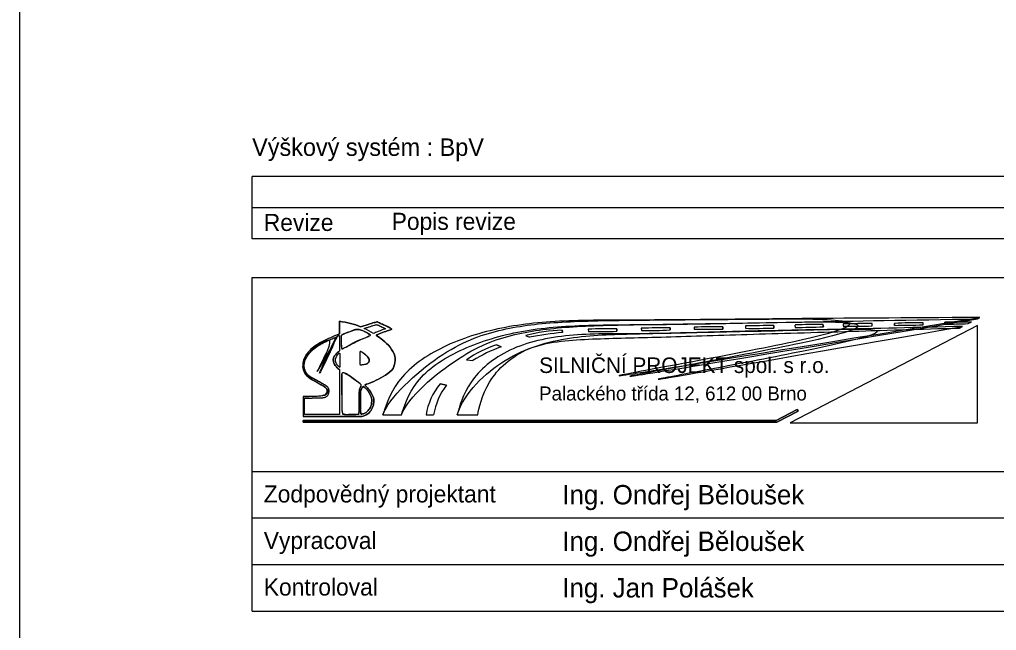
# Model space of a CAD drawing. Extents: x -598463 to -597973, y -1203201 to -1202904.
# Drawn here: x -598183.2 to -598057.2, y -1203061.8 to -1202983 of the extents above; entities that cross this region are included whole.
import ezdxf

# ---------------------------------------------------------------- set-up
doc = ezdxf.new("R2010")
doc.units = 0
for name, color, linetype in [('AQP_ROZPISKA', 7, 'Continuous'), ('geom_Pomoc', 7, 'Continuous'), ('sil_popis_legenda', 7, 'Continuous')]:
    doc.layers.add(name, color=color, linetype=linetype)

msp = doc.modelspace()

# ---------------------------------------------------------------- linework, layer by layer
at = {"layer": 'AQP_ROZPISKA'}
for p, q in [((-597983.21, -1203003.29), (-598153.21, -1203003.29)), ((-598153.21, -1203011.29), (-598153.21, -1203003.29)), ((-597983.21, -1203007.29), (-598153.21, -1203007.29)), ((-597983.21, -1203011.29), (-598153.21, -1203011.29)), ((-598141.96, -1203023.56), (-598141.96, -1203021.94)), ((-598141.96, -1203021.94), (-598141.96, -1203023.56)), ((-598089.57, -1203022.54), (-598089.59, -1203022.84)), ((-598089.57, -1203022.54), (-598089.59, -1203022.84)), ((-598085.93, -1203022.48), (-598085.91, -1203022.8)), ((-598085.91, -1203022.8), (-598085.93, -1203022.48)), ((-598059.65, -1203022.46), (-598083.83, -1203035.04)), ((-598059.65, -1203022.46), (-598083.83, -1203035.04)), ((-598083.19, -1203022.42), (-598083.18, -1203022.73)), ((-598083.19, -1203022.42), (-598083.18, -1203022.73)), ((-598079.58, -1203022.35), (-598079.52, -1203022.66)), ((-598079.52, -1203022.66), (-598079.58, -1203022.35)), ((-598076.97, -1203022.28), (-598076.96, -1203022.58)), ((-598076.97, -1203022.28), (-598076.96, -1203022.58)), ((-598073.23, -1203022.53), (-598073.24, -1203022.21)), ((-598073.23, -1203022.53), (-598073.24, -1203022.21)), ((-598070.34, -1203022.46), (-598070.36, -1203022.2)), ((-598070.36, -1203022.2), (-598070.34, -1203022.46)), ((-598066.67, -1203022.4), (-598066.67, -1203022.13)), ((-598066.67, -1203022.4), (-598066.67, -1203022.13)), ((-598063.89, -1203022.06), (-598063.9, -1203022.29)), ((-598063.89, -1203022.06), (-598063.9, -1203022.29)), ((-598061.97, -1203022.8), (-598061.6, -1203022.6)), ((-598061.97, -1203022.8), (-598061.6, -1203022.6)), ((-598060.87, -1203022.23), (-598060.45, -1203022.04)), ((-598060.87, -1203022.23), (-598060.45, -1203022.04)), ((-598059.65, -1203035.04), (-598059.65, -1203022.46)), ((-598059.65, -1203035.04), (-598059.65, -1203022.46)), ((-598059.63, -1203021.63), (-598059.33, -1203021.44)), ((-598059.63, -1203021.63), (-598059.33, -1203021.44)), ((-598141.96, -1203023.78), (-598141.96, -1203025.76)), ((-598141.96, -1203023.78), (-598141.96, -1203025.76)), ((-598117.93, -1203023.76), (-598117.44, -1203023.98)), ((-598117.93, -1203023.76), (-598117.44, -1203023.98)), ((-598113.21, -1203023.07), (-598113.18, -1203023.36)), ((-598113.18, -1203023.36), (-598113.21, -1203023.07)), ((-598109.85, -1203022.96), (-598109.84, -1203023.24)), ((-598109.85, -1203022.96), (-598109.84, -1203023.24)), ((-598106.15, -1203022.9), (-598106.18, -1203023.22)), ((-598106.18, -1203023.22), (-598106.15, -1203022.9)), ((-598103.03, -1203022.84), (-598102.98, -1203023.13)), ((-598103.03, -1203022.84), (-598102.98, -1203023.13)), ((-598099.3, -1203022.76), (-598099.29, -1203023.05)), ((-598099.29, -1203023.05), (-598099.3, -1203022.76)), ((-598096.19, -1203022.69), (-598096.2, -1203022.97)), ((-598096.19, -1203022.69), (-598096.2, -1203022.97)), ((-598092.49, -1203022.64), (-598092.51, -1203022.95)), ((-598092.51, -1203022.95), (-598092.49, -1203022.64)), ((-598121.7, -1203024.98), (-598121.1, -1203025.24)), ((-598121.1, -1203025.24), (-598121.7, -1203024.98)), ((-598125.54, -1203026.9), (-598124.73, -1203027.01)), ((-598125.54, -1203026.9), (-598124.73, -1203027.01)), ((-598141.96, -1203028.16), (-598141.96, -1203033.93)), ((-598141.96, -1203028.16), (-598141.96, -1203033.93)), ((-598128.97, -1203030), (-598128.16, -1203030.16)), ((-598128.16, -1203030.16), (-598128.97, -1203030)), ((-598146.63, -1203031.63), (-598146.63, -1203034.21)), ((-598146.63, -1203031.63), (-598146.63, -1203034.21)), ((-598146.46, -1203033.93), (-598146.46, -1203031.83)), ((-598146.46, -1203033.93), (-598146.46, -1203031.83)), ((-598141.96, -1203033.93), (-598146.46, -1203033.93)), ((-598141.96, -1203033.93), (-598146.46, -1203033.93)), ((-598085.62, -1203034.72), (-598082.89, -1203033.31)), ((-598082.89, -1203033.31), (-598085.62, -1203034.72)), ((-598082.78, -1203033.52), (-598085.55, -1203034.96)), ((-598085.55, -1203034.96), (-598082.78, -1203033.52)), ((-598082.89, -1203033.31), (-598082.78, -1203033.52)), ((-598082.78, -1203033.52), (-598082.89, -1203033.31)), ((-598139.73, -1203034.21), (-598146.63, -1203034.21)), ((-598146.63, -1203034.21), (-598140.27, -1203034.21)), ((-598146.61, -1203034.72), (-598085.62, -1203034.72)), ((-598146.61, -1203034.96), (-598146.61, -1203034.72)), ((-598146.61, -1203034.72), (-598146.61, -1203034.96)), ((-598085.62, -1203034.72), (-598146.61, -1203034.72)), ((-598085.55, -1203034.96), (-598146.61, -1203034.96)), ((-598146.61, -1203034.96), (-598085.55, -1203034.96)), ((-598136.34, -1203033.98), (-598133.94, -1203033.98)), ((-598136.34, -1203033.98), (-598133.94, -1203033.98)), ((-598130.78, -1203034), (-598129.8, -1203034)), ((-598130.78, -1203034), (-598129.8, -1203034)), ((-598126.75, -1203033.98), (-598124.1, -1203033.98)), ((-598126.75, -1203033.98), (-598124.1, -1203033.98)), ((-598083.83, -1203035.04), (-598059.65, -1203035.04)), ((-598083.83, -1203035.04), (-598059.65, -1203035.04)), ((-598153.21, -1203041.29), (-597983.21, -1203041.29)), ((-598153.21, -1203059.29), (-598153.21, -1203041.29)), ((-598153.21, -1203047.29), (-597983.21, -1203047.29)), ((-598153.21, -1203053.29), (-597983.21, -1203053.29)), ((-598153.21, -1203059.29), (-597983.21, -1203059.29))]:
    msp.add_line(p, q, dxfattribs=at)
msp.add_lwpolyline([(-598153.21, -1203041.29), (-598153.21, -1203016.29), (-597983.21, -1203016.29), (-597983.21, -1203041.29)], dxfattribs=at)
for centre, radius, start, end in [((-598085.31, -1203177.66), 155.18, 90.2294, 91.5724), ((-598085.31, -1203177.66), 155.18, 90.2294, 91.5724), ((-598079.99, -1203097.29), 74.95, 89.6826, 92.4426), ((-598079.99, -1203097.29), 74.95, 89.6826, 92.4426), ((-598072.72, -1203140.64), 118.43, 90.2515, 92.0562), ((-598072.72, -1203140.64), 118.43, 90.2515, 92.0562), ((-598076.07, -1202948), 74.58, 269.3163, 272.1867), ((-598076.07, -1202948), 74.58, 269.3163, 272.1867), ((-598066.97, -1203103.23), 81.1, 89.7918, 92.3956), ((-598066.97, -1203103.23), 81.1, 89.7918, 92.3956), ((-598071.15, -1202858.28), 164.18, 270.2842, 271.5636), ((-598071.15, -1202858.28), 164.18, 270.2842, 271.5636), ((-598064.12, -1202933.23), 89.07, 270.1435, 272.0944), ((-598064.12, -1202933.23), 89.07, 270.1435, 272.0944), ((-598061.79, -1203090.03), 68, 88.8652, 91.7643), ((-598061.79, -1203090.03), 68, 88.8652, 91.7643), ((-598142.66, -1203031.32), 9.33, 56.8705, 65.2304), ((-598142.66, -1203031.32), 9.33, 56.8705, 65.2304), ((-598112.28, -1203045.9), 22.85, 92.3231, 104.3036), ((-598112.28, -1203045.9), 22.85, 92.3231, 104.3036), ((-598105.61, -1203090.56), 67.62, 96.4292, 100.0816), ((-598105.61, -1203090.56), 67.62, 96.4292, 100.0816), ((-598106.93, -1203086.14), 63.25, 89.2956, 92.6521), ((-598106.93, -1203086.14), 63.25, 89.2956, 92.6521), ((-598108.77, -1202885.41), 137.84, 269.5563, 271.078), ((-598108.77, -1202885.41), 137.84, 269.5563, 271.078), ((-598099.5, -1203099.04), 76.28, 89.8478, 92.65), ((-598099.5, -1203099.04), 76.28, 89.8478, 92.65), ((-598102.23, -1202971.58), 51.55, 269.1683, 273.2631), ((-598102.23, -1202971.58), 51.55, 269.1683, 273.2631), ((-598094.89, -1202941.39), 81.58, 269.0793, 271.6663), ((-598094.89, -1202941.39), 81.58, 269.0793, 271.6663), ((-598093.51, -1203080.9), 58.27, 88.9978, 92.631), ((-598093.51, -1203080.9), 58.27, 88.9978, 92.631), ((-598088.49, -1202954.26), 68.59, 269.077, 272.1517), ((-598088.49, -1202954.26), 68.59, 269.077, 272.1517), ((-598084.11, -1202888.1), 134.63, 270.3941, 271.9528), ((-598084.11, -1202888.1), 134.63, 270.3941, 271.9528), ((-598116.88, -1203039.39), 15.2, 108.4834, 124.7543), ((-598116.88, -1203039.39), 15.2, 108.4834, 124.7543), ((-598114.98, -1203042.43), 18.25, 109.6001, 122.294), ((-598114.98, -1203042.43), 18.25, 109.6001, 122.294), ((-598122.6, -1203035.29), 8.28, 140.293, 171.0099), ((-598122.6, -1203035.29), 8.28, 140.293, 171.0099), ((-598120.88, -1203035.54), 9.05, 143.5312, 170.2141), ((-598120.88, -1203035.54), 9.05, 143.5312, 170.2141)]:
    msp.add_arc(centre, radius, start, end, dxfattribs=at)
for points, degree in [([(-598141.96, -1203021.94), (-598141.44, -1203022.02), (-598140.51, -1203022.17), (-598139.61, -1203022.48), (-598139.22, -1203022.65)], 3), ([(-598139.22, -1203022.65), (-598139.61, -1203022.48), (-598140.51, -1203022.17), (-598141.44, -1203022.02), (-598141.96, -1203021.94)], 3), ([(-598139.22, -1203022.65), (-598138.63, -1203022.46), (-598137.98, -1203022.24), (-598137.27, -1203022.05), (-598137.11, -1203022), (-598136.99, -1203022.04), (-598136.84, -1203022.12), (-598136.28, -1203022.39), (-598135.66, -1203022.65), (-598135.25, -1203022.89), (-598135.17, -1203022.93), (-598135.24, -1203022.99), (-598135.42, -1203023.04), (-598136.12, -1203023.28), (-598136.75, -1203023.53), (-598137.23, -1203023.73)], 3), ([(-598137.23, -1203023.73), (-598136.75, -1203023.53), (-598136.12, -1203023.28), (-598135.42, -1203023.04), (-598135.24, -1203022.99), (-598135.17, -1203022.93), (-598135.25, -1203022.89), (-598135.66, -1203022.65), (-598136.28, -1203022.39), (-598136.84, -1203022.12), (-598136.99, -1203022.04), (-598137.11, -1203022), (-598137.27, -1203022.05), (-598137.98, -1203022.24), (-598138.63, -1203022.46), (-598139.22, -1203022.65)], 3), ([(-598138.75, -1203022.85), (-598138.61, -1203022.8), (-598138.35, -1203022.72), (-598137.96, -1203022.6), (-598137.57, -1203022.48), (-598137.29, -1203022.41), (-598137.13, -1203022.36), (-598137.11, -1203022.36)], 3), ([(-598138.75, -1203022.85), (-598138.61, -1203022.8), (-598138.35, -1203022.72), (-598137.96, -1203022.6), (-598137.57, -1203022.48), (-598137.29, -1203022.41), (-598137.13, -1203022.36), (-598137.11, -1203022.36)], 3), ([(-598137.11, -1203022.36), (-598137.09, -1203022.37), (-598137, -1203022.41), (-598136.85, -1203022.49), (-598136.59, -1203022.61), (-598136.31, -1203022.74), (-598136.09, -1203022.84), (-598135.99, -1203022.89)], 3), ([(-598137.11, -1203022.36), (-598137.09, -1203022.37), (-598137, -1203022.41), (-598136.85, -1203022.49), (-598136.59, -1203022.61), (-598136.31, -1203022.74), (-598136.09, -1203022.84), (-598135.99, -1203022.89)], 3), ([(-598136.34, -1203033.98), (-598135.58, -1203031.8), (-598128.64, -1203025.4), (-598121.35, -1203022.86), (-598114.2, -1203021.95), (-598104.63, -1203021.78), (-598088.87, -1203021.66), (-598059.33, -1203021.44), (-598136.34, -1203033.98), (-598059.33, -1203021.44)], 3), ([(-598059.33, -1203021.44), (-598069.18, -1203021.5), (-598084.28, -1203021.59), (-598102.57, -1203021.82), (-598113.41, -1203021.74), (-598121.59, -1203022.65), (-598129.26, -1203025.17), (-598134.98, -1203029.47), (-598136.12, -1203033.24), (-598136.34, -1203033.98)], 3), ([(-598133.94, -1203033.98), (-598133.18, -1203031.8), (-598125.97, -1203025.6), (-598118.94, -1203023.31), (-598111.66, -1203022.5), (-598102.07, -1203022.35), (-598086.08, -1203022.1), (-598059.63, -1203021.63), (-598133.94, -1203033.98), (-598059.63, -1203021.63)], 3), ([(-598133.94, -1203033.98), (-598133.72, -1203033.24), (-598132.59, -1203029.43), (-598126.65, -1203025.46), (-598119.04, -1203023.05), (-598110.9, -1203022.34), (-598099.94, -1203022.39), (-598082.59, -1203022.01), (-598068.45, -1203021.77), (-598059.63, -1203021.63)], 3), ([(-598126.75, -1203033.98), (-598125.8, -1203031.13), (-598120.68, -1203026.11), (-598112.26, -1203023.76), (-598103.94, -1203023.55), (-598094.68, -1203023.35), (-598079.02, -1203022.99), (-598061.6, -1203022.6), (-598126.75, -1203033.98), (-598061.6, -1203022.6)], 3), ([(-598061.6, -1203022.6), (-598067.41, -1203022.74), (-598078.43, -1203023), (-598092.55, -1203023.26), (-598103.62, -1203023.64), (-598112.41, -1203023.43), (-598120.44, -1203025.21), (-598125.61, -1203029.7), (-598126.49, -1203033), (-598126.75, -1203033.98)], 3), ([(-598142.04, -1203023.59), (-598142.77, -1203023.9), (-598144.2, -1203024.49), (-598146.01, -1203025.69), (-598146.75, -1203027.13), (-598146.68, -1203028.21), (-598146.28, -1203028.99), (-598145.17, -1203029.66), (-598144.27, -1203030.11), (-598143.52, -1203030.59), (-598143.46, -1203031.03), (-598143.67, -1203031.57), (-598144.97, -1203031.62), (-598145.92, -1203031.62), (-598146.63, -1203031.63)], 3), ([(-598146.63, -1203031.63), (-598144.38, -1203031.6), (-598143.67, -1203031.41), (-598143.5, -1203031.03), (-598143.59, -1203030.59), (-598143.85, -1203030.38), (-598145.39, -1203029.51), (-598146.22, -1203028.91), (-598146.67, -1203028.04), (-598146.7, -1203027.56), (-598146, -1203025.96), (-598144.21, -1203024.58), (-598142.04, -1203023.59), (-598146.63, -1203031.63), (-598142.04, -1203023.59)], 3), ([(-598146.46, -1203031.83), (-598146.22, -1203031.83), (-598145.83, -1203031.83), (-598145.27, -1203031.82), (-598144.8, -1203031.81), (-598144.38, -1203031.8), (-598144.07, -1203031.79), (-598143.89, -1203031.75), (-598143.75, -1203031.71), (-598143.62, -1203031.64), (-598143.5, -1203031.54), (-598143.4, -1203031.41), (-598143.34, -1203031.27), (-598143.3, -1203031.12), (-598143.28, -1203030.96), (-598143.29, -1203030.81), (-598143.32, -1203030.65), (-598143.39, -1203030.5), (-598143.49, -1203030.38), (-598143.61, -1203030.29), (-598143.82, -1203030.16), (-598144.27, -1203029.9), (-598144.81, -1203029.6), (-598145.28, -1203029.34), (-598145.54, -1203029.19), (-598145.73, -1203029.07), (-598145.9, -1203028.94), (-598146.05, -1203028.8), (-598146.19, -1203028.64), (-598146.3, -1203028.46), (-598146.39, -1203028.27), (-598146.46, -1203028.07), (-598146.5, -1203027.87), (-598146.51, -1203027.66), (-598146.49, -1203027.45), (-598146.46, -1203027.25), (-598146.4, -1203027.04), (-598146.32, -1203026.84), (-598146.22, -1203026.64), (-598146.11, -1203026.45), (-598145.98, -1203026.26), (-598145.84, -1203026.08), (-598145.7, -1203025.91), (-598145.54, -1203025.75), (-598145.37, -1203025.6), (-598145.14, -1203025.41), (-598144.84, -1203025.19), (-598144.46, -1203024.95), (-598144.06, -1203024.73), (-598143.65, -1203024.52), (-598143.23, -1203024.32), (-598142.67, -1203024.07), (-598142.25, -1203023.9), (-598141.96, -1203023.78)], 3), ([(-598142.04, -1203023.59), (-598142.01, -1203023.58), (-598141.99, -1203023.57), (-598141.96, -1203023.56)], 2), ([(-598141.96, -1203023.56), (-598141.99, -1203023.57), (-598142.01, -1203023.58), (-598142.04, -1203023.59)], 2), ([(-598141.71, -1203023.82), (-598141.71, -1203023.79), (-598141.7, -1203023.72), (-598141.3, -1203023.48), (-598140.64, -1203023.32), (-598139.84, -1203022.91), (-598139.23, -1203023.02), (-598138.8, -1203023.23), (-598138.46, -1203023.38), (-598137.78, -1203023.73), (-598138.17, -1203023.85), (-598138.74, -1203024.1), (-598139.99, -1203024.58), (-598140.83, -1203025.14), (-598141.71, -1203025.56), (-598141.7, -1203025.24), (-598141.72, -1203024.75), (-598141.72, -1203024.22), (-598141.71, -1203023.82)], 3), ([(-598141.71, -1203023.82), (-598141.69, -1203023.73), (-598141.61, -1203023.67), (-598140.58, -1203023.26), (-598139.69, -1203022.98), (-598139.19, -1203023.06), (-598138.85, -1203023.21), (-598138.4, -1203023.42), (-598137.98, -1203023.76), (-598138.19, -1203023.87), (-598138.31, -1203023.91), (-598139.8, -1203024.55), (-598141.52, -1203025.47), (-598141.66, -1203025.51), (-598141.7, -1203025.32), (-598141.71, -1203024.98), (-598141.71, -1203023.82), (-598141.71, -1203023.82), (-598141.71, -1203023.82)], 3), ([(-598137.23, -1203023.73), (-598137.18, -1203023.77), (-598136.58, -1203024.17), (-598135.61, -1203024.95), (-598134.78, -1203026.14), (-598134.72, -1203027.26), (-598135.05, -1203028.28), (-598136.32, -1203029.08), (-598137.49, -1203029.71), (-598138.43, -1203030.01), (-598138.68, -1203030.18)], 3), ([(-598138.68, -1203030.18), (-598138.43, -1203030.01), (-598137.49, -1203029.71), (-598136.32, -1203029.08), (-598135.05, -1203028.28), (-598134.72, -1203027.26), (-598134.78, -1203026.14), (-598135.61, -1203024.95), (-598136.58, -1203024.17), (-598137.18, -1203023.77), (-598137.23, -1203023.73)], 3), ([(-598135.99, -1203022.89), (-598136.06, -1203022.91), (-598136.26, -1203022.98), (-598136.59, -1203023.11), (-598137.05, -1203023.29), (-598137.37, -1203023.42), (-598137.56, -1203023.51)], 3), ([(-598135.99, -1203022.89), (-598136.06, -1203022.91), (-598136.26, -1203022.98), (-598136.59, -1203023.11), (-598137.05, -1203023.29), (-598137.37, -1203023.42), (-598137.56, -1203023.51)], 3), ([(-598124.1, -1203033.98), (-598123.96, -1203033.25), (-598123.33, -1203029.71), (-598117.97, -1203024.77), (-598109.88, -1203024.16), (-598101.46, -1203024.03), (-598090.53, -1203023.64), (-598077.06, -1203023.27), (-598066.91, -1203022.95), (-598061.97, -1203022.8)], 3), ([(-598124.1, -1203033.98), (-598123.96, -1203033.25), (-598123.33, -1203029.71), (-598117.97, -1203024.77), (-598109.88, -1203024.16), (-598101.46, -1203024.03), (-598090.53, -1203023.64), (-598077.06, -1203023.27), (-598066.91, -1203022.95), (-598061.97, -1203022.8)], 3), ([(-598146.46, -1203031.83), (-598145.74, -1203031.83), (-598145.28, -1203031.82), (-598144.8, -1203031.81), (-598144.3, -1203031.8), (-598144.03, -1203031.78), (-598143.89, -1203031.75), (-598143.76, -1203031.71), (-598143.62, -1203031.64), (-598143.5, -1203031.53), (-598143.41, -1203031.41), (-598143.34, -1203031.26), (-598143.3, -1203031.12), (-598143.29, -1203030.96), (-598143.29, -1203030.81), (-598143.33, -1203030.66), (-598143.4, -1203030.51), (-598143.5, -1203030.38), (-598143.62, -1203030.29), (-598143.73, -1203030.22), (-598144.14, -1203029.97), (-598144.95, -1203029.53), (-598145.35, -1203029.3), (-598145.54, -1203029.19), (-598145.73, -1203029.07), (-598145.9, -1203028.94), (-598146.05, -1203028.79), (-598146.19, -1203028.63), (-598146.3, -1203028.46), (-598146.39, -1203028.27), (-598146.46, -1203028.07), (-598146.49, -1203027.87), (-598146.5, -1203027.66), (-598146.49, -1203027.45), (-598146.45, -1203027.25), (-598146.4, -1203027.04), (-598146.32, -1203026.84), (-598146.22, -1203026.64), (-598146.11, -1203026.45), (-598145.98, -1203026.26), (-598145.84, -1203026.08), (-598145.69, -1203025.92), (-598145.54, -1203025.76), (-598145.37, -1203025.6), (-598145.2, -1203025.46), (-598144.84, -1203025.2), (-598144.46, -1203024.95), (-598144.06, -1203024.73), (-598143.65, -1203024.52), (-598143.23, -1203024.33), (-598142.81, -1203024.14), (-598141.96, -1203023.78), (-598146.1, -1203031.83), (-598142.39, -1203023.96)], 3), ([(-598141.96, -1203028.16), (-598142.07, -1203028.07), (-598142.34, -1203027.83), (-598142.69, -1203027.42), (-598142.76, -1203026.96), (-598142.71, -1203026.54), (-598142.4, -1203026.15), (-598142.13, -1203025.9), (-598141.96, -1203025.76)], 3), ([(-598141.96, -1203025.76), (-598142.13, -1203025.9), (-598142.4, -1203026.15), (-598142.71, -1203026.54), (-598142.76, -1203026.96), (-598142.69, -1203027.42), (-598142.34, -1203027.83), (-598142.07, -1203028.07), (-598141.96, -1203028.16)], 3), ([(-598141.94, -1203027.86), (-598142.33, -1203027.5), (-598142.49, -1203027.02), (-598142.44, -1203026.61), (-598142.08, -1203026.11), (-598141.91, -1203025.99), (-598141.91, -1203026.17), (-598141.91, -1203026.95), (-598141.91, -1203027.48), (-598141.89, -1203027.74), (-598141.92, -1203027.88), (-598141.94, -1203027.86), (-598141.92, -1203027.88)], 3), ([(-598139.32, -1203026.39), (-598139.32, -1203026.29), (-598139.32, -1203026.13), (-598139.31, -1203025.97), (-598139.31, -1203025.82), (-598139.17, -1203025.82), (-598139.04, -1203025.93), (-598138.81, -1203026.07), (-598138.55, -1203026.28), (-598138.28, -1203026.51), (-598138.06, -1203026.78), (-598138.08, -1203027.05), (-598138.18, -1203027.25), (-598138.37, -1203027.42), (-598138.67, -1203027.47), (-598138.94, -1203027.52), (-598139.12, -1203027.53), (-598139.22, -1203027.54), (-598139.3, -1203027.53), (-598139.31, -1203027.43), (-598139.32, -1203027.25), (-598139.32, -1203026.88), (-598139.32, -1203026.57), (-598139.32, -1203026.39)], 3), ([(-598139.32, -1203026.39), (-598139.32, -1203026.1), (-598139.31, -1203025.93), (-598139.29, -1203025.84), (-598139.22, -1203025.83), (-598139.07, -1203025.91), (-598138.83, -1203026.07), (-598138.57, -1203026.27), (-598138.27, -1203026.54), (-598138.1, -1203026.8), (-598138.1, -1203027.08), (-598138.19, -1203027.23), (-598138.34, -1203027.37), (-598138.69, -1203027.47), (-598138.98, -1203027.52), (-598139.16, -1203027.54), (-598139.23, -1203027.54), (-598139.29, -1203027.52), (-598139.31, -1203027.46), (-598139.32, -1203027.31), (-598139.32, -1203026.96), (-598139.32, -1203026.39), (-598139.32, -1203026.39), (-598139.32, -1203026.39)], 3), ([(-598141.66, -1203032.07), (-598141.66, -1203031.45), (-598141.67, -1203030.6), (-598141.66, -1203029.47), (-598141.67, -1203028.99), (-598141.66, -1203028.43), (-598140.81, -1203028.79), (-598140.2, -1203029.34), (-598139.49, -1203029.83), (-598139.06, -1203030.15), (-598139.22, -1203030.43), (-598139.42, -1203030.77), (-598139.37, -1203031.91), (-598139.37, -1203032.9), (-598139.42, -1203033.73), (-598139.38, -1203033.93), (-598140.17, -1203033.93), (-598140.74, -1203033.92), (-598141.66, -1203033.96), (-598141.64, -1203033.05), (-598141.65, -1203032.5), (-598141.66, -1203032.07)], 3), ([(-598141.66, -1203032.07), (-598141.66, -1203030.19), (-598141.66, -1203029.49), (-598141.66, -1203028.79), (-598141.6, -1203028.52), (-598141.31, -1203028.58), (-598140.05, -1203029.42), (-598139.22, -1203030.03), (-598139.11, -1203030.16), (-598139.17, -1203030.34), (-598139.36, -1203030.75), (-598139.39, -1203031.32), (-598139.42, -1203033.6), (-598139.42, -1203033.67), (-598139.46, -1203033.93), (-598139.52, -1203033.93), (-598141.36, -1203033.94), (-598141.55, -1203033.93), (-598141.65, -1203033.52), (-598141.66, -1203032.07), (-598141.66, -1203032.07), (-598141.66, -1203032.07)], 3), ([(-598138.68, -1203030.18), (-598138.65, -1203030.21), (-598138.34, -1203030.48), (-598137.92, -1203031.05), (-598137.5, -1203031.73), (-598137.49, -1203032.57), (-598137.76, -1203033.32), (-598138.24, -1203033.93), (-598139.11, -1203034.27), (-598139.65, -1203034.2), (-598140.56, -1203034.22), (-598140, -1203034.21), (-598139.73, -1203034.21)], 3), ([(-598140.27, -1203034.21), (-598140.27, -1203034.21), (-598140.26, -1203034.21), (-598139.65, -1203034.2), (-598139.11, -1203034.27), (-598138.24, -1203033.93), (-598137.76, -1203033.32), (-598137.49, -1203032.57), (-598137.5, -1203031.73), (-598137.92, -1203031.05), (-598138.34, -1203030.48), (-598138.65, -1203030.21), (-598138.68, -1203030.18)], 3), ([(-598138.86, -1203030.32), (-598138.87, -1203030.33), (-598139.02, -1203030.47), (-598139.24, -1203030.82), (-598139.22, -1203031.5), (-598139.24, -1203032.09), (-598139.23, -1203032.75), (-598139.24, -1203033.3), (-598139.21, -1203033.72), (-598139.19, -1203033.88)], 3), ([(-598139.19, -1203033.88), (-598139.21, -1203033.72), (-598139.24, -1203033.3), (-598139.23, -1203032.75), (-598139.24, -1203032.09), (-598139.22, -1203031.5), (-598139.24, -1203030.82), (-598139.02, -1203030.47), (-598138.87, -1203030.33), (-598138.86, -1203030.32)], 3), ([(-598139.19, -1203033.88), (-598139.17, -1203033.89), (-598139.09, -1203033.9), (-598138.87, -1203033.86), (-598138.48, -1203033.75), (-598138.15, -1203033.33), (-598137.85, -1203032.89), (-598137.79, -1203032.43), (-598137.76, -1203032.01), (-598137.85, -1203031.65), (-598138.02, -1203031.32), (-598138.26, -1203030.94), (-598138.52, -1203030.6), (-598138.76, -1203030.4), (-598138.85, -1203030.34), (-598138.86, -1203030.32)], 3), ([(-598138.86, -1203030.32), (-598138.85, -1203030.34), (-598138.76, -1203030.4), (-598138.52, -1203030.6), (-598138.26, -1203030.94), (-598138.02, -1203031.32), (-598137.85, -1203031.65), (-598137.76, -1203032.01), (-598137.79, -1203032.43), (-598137.85, -1203032.89), (-598138.15, -1203033.33), (-598138.48, -1203033.75), (-598138.87, -1203033.86), (-598139.09, -1203033.9), (-598139.17, -1203033.89), (-598139.19, -1203033.88)], 3)]:
    msp.add_open_spline(points, degree=degree, dxfattribs=at)
at = {"layer": 'geom_Pomoc'}
msp.add_line((-598183.21, -1202904.29), (-598183.21, -1203196.29), dxfattribs=at)

# ---------------------------------------------------------------- texts
at = {"layer": 'AQP_ROZPISKA'}
for s, height, p in [('Revize', 2.2, (-598151.71, -1203010.29)), ('Popis revize', 2.2, (-598135.21, -1203010.15)), ('SILNIČNÍ PROJEKT spol. s r.o.', 2, (-598116.19, -1203028.6)), ('Palackého třída 12, 612 00 Brno', 1.8, (-598116.19, -1203032.14)), ('Zodpovědný projektant', 2.2, (-598151.71, -1203045.29)), ('Ing. Ondřej Běloušek', 2.5, (-598113.21, -1203045.54)), ('Vypracoval', 2.2, (-598151.71, -1203051.29)), ('Ing. Ondřej Běloušek', 2.5, (-598113.21, -1203051.54)), ('Kontroloval', 2.2, (-598151.71, -1203057.29)), ('Ing. Jan Polášek', 2.5, (-598113.21, -1203057.54))]:
    msp.add_text(s, height=height, rotation=360, dxfattribs=at).set_placement(p)
at = {"layer": 'sil_popis_legenda'}
msp.add_text('Výškový systém : BpV', height=2.26, rotation=359.9812, dxfattribs=at).set_placement((-598153.21, -1203000.61))

doc.saveas('drawing.dxf')
